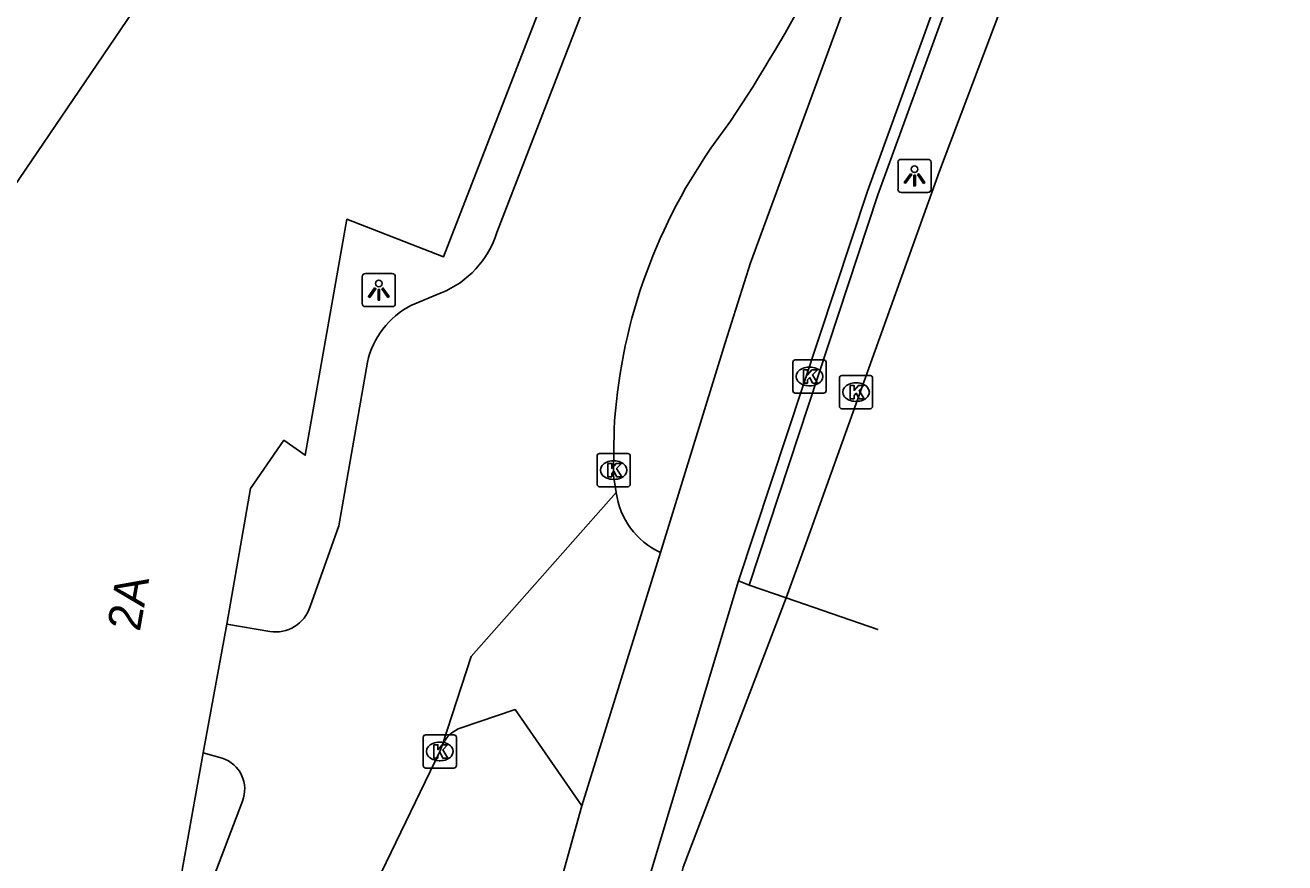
# Model space of a CAD drawing. Extents: x 158132 to 159658, y 385257 to 387209.
# Drawn here: x 159315.62 to 159353.57, y 385360.69 to 385385.92 of the extents above; entities that cross this region are included whole.
import ezdxf

# ---------------------------------------------------------------- set-up
doc = ezdxf.new("R2010")
doc.units = 0
for name, color, linetype in [('IMGEO_Berm_open', 7, 'Continuous'), ('IMGEO_Fietspad_gesloten', 7, 'Continuous'), ('IMGEO_Kolk', 7, 'Continuous'), ('IMGEO_Lichtpunt', 7, 'Continuous'), ('IMGEO_Pand', 7, 'Continuous'), ('IMGEO_Pand_nummerreeks', 7, 'Continuous'), ('IMGEO_Parkeervlak_open', 7, 'Continuous'), ('IMGEO_Rijbaan_lokaal_gesloten', 7, 'Continuous'), ('IMGEO_Rijbaan_lokaal_open', 7, 'Continuous'), ('IMGEO_Voetpad_open', 7, 'Continuous')]:
    doc.layers.add(name, color=color, linetype=linetype)

msp = doc.modelspace()

# ---------------------------------------------------------------- linework, layer by layer
at = {"layer": 'IMGEO_Berm_open'}
msp.add_lwpolyline([(159337.434, 385369.055), (159341.31, 385380.813), (159345.777, 385393.089)], dxfattribs=at)
at = {"layer": 'IMGEO_Fietspad_gesloten'}
for points in [[(159353.565, 385414.672), (159347.632, 385399.1), (159345.432, 385393.179), (159340.99, 385380.922), (159337.107, 385369.181)], [(159334.755, 385370.041), (159336.71, 385376.358), (159337.469, 385378.764), (159341.578, 385389.943)], [(159332.393, 385362.406), (159334.755, 385370.041)], [(159325.605, 385338.172), (159326.704, 385341.948), (159332.393, 385362.406)]]:
    msp.add_lwpolyline(points, dxfattribs=at)
at = {"layer": 'IMGEO_Kolk'}
for p, q in [((159338.745, 385374.916), (159338.745, 385375.768)), ((159338.82, 385375.842), (159339.672, 385375.842)), ((159339.746, 385375.768), (159339.746, 385374.916)), ((159339.233, 385375.622), (159339.258, 385375.622)), ((159340.223, 385375.371), (159341.075, 385375.371)), ((159339.256, 385375.062), (159339.231, 385375.062)), ((159340.148, 385374.445), (159340.148, 385375.297)), ((159340.636, 385375.151), (159340.661, 385375.151)), ((159341.149, 385375.297), (159341.149, 385374.445)), ((159339.672, 385374.842), (159338.82, 385374.842)), ((159340.659, 385374.591), (159340.634, 385374.591)), ((159341.075, 385374.371), (159340.223, 385374.371)), ((159332.846, 385372.095), (159332.846, 385372.947)), ((159332.921, 385373.021), (159333.773, 385373.021)), ((159333.334, 385372.801), (159333.359, 385372.801)), ((159333.847, 385372.947), (159333.847, 385372.095)), ((159333.773, 385372.021), (159332.921, 385372.021)), ((159333.357, 385372.241), (159333.332, 385372.241)), ((159327.609, 385363.62), (159327.609, 385364.472)), ((159327.684, 385364.546), (159328.536, 385364.546)), ((159328.61, 385364.472), (159328.61, 385363.62)), ((159328.097, 385364.326), (159328.122, 385364.326)), ((159328.12, 385363.766), (159328.095, 385363.766)), ((159328.536, 385363.546), (159327.684, 385363.546))]:
    msp.add_line(p, q, dxfattribs=at)
for points in [[(159338.745, 385374.916), (159338.745, 385375.768)], [(159338.82, 385375.842), (159339.672, 385375.842)], [(159339.746, 385375.768), (159339.746, 385374.916)], [(159339.066, 385375.542), (159339.189, 385375.542), (159339.189, 385375.391), (159339.319, 385375.542), (159339.483, 385375.542), (159339.337, 385375.391), (159339.49, 385375.142), (159339.338, 385375.142), (159339.253, 385375.306), (159339.189, 385375.239), (159339.189, 385375.142), (159339.066, 385375.142), (159339.066, 385375.542)], [(159340.223, 385375.371), (159341.075, 385375.371)], [(159340.148, 385374.445), (159340.148, 385375.297)], [(159340.469, 385375.071), (159340.592, 385375.071), (159340.592, 385374.92), (159340.722, 385375.071), (159340.886, 385375.071), (159340.74, 385374.92), (159340.893, 385374.671), (159340.741, 385374.671), (159340.656, 385374.835), (159340.592, 385374.768), (159340.592, 385374.671), (159340.469, 385374.671), (159340.469, 385375.071)], [(159341.149, 385375.297), (159341.149, 385374.445)], [(159339.672, 385374.842), (159338.82, 385374.842)], [(159341.075, 385374.371), (159340.223, 385374.371)], [(159332.846, 385372.095), (159332.846, 385372.947)], [(159332.921, 385373.021), (159333.773, 385373.021)], [(159333.167, 385372.721), (159333.29, 385372.721), (159333.29, 385372.57), (159333.42, 385372.721), (159333.584, 385372.721), (159333.438, 385372.57), (159333.591, 385372.321), (159333.439, 385372.321), (159333.354, 385372.485), (159333.29, 385372.418), (159333.29, 385372.321), (159333.167, 385372.321), (159333.167, 385372.721)], [(159333.847, 385372.947), (159333.847, 385372.095)], [(159333.773, 385372.021), (159332.921, 385372.021)], [(159327.609, 385363.62), (159327.609, 385364.472)], [(159327.684, 385364.546), (159328.536, 385364.546)], [(159328.61, 385364.472), (159328.61, 385363.62)], [(159327.93, 385364.246), (159328.053, 385364.246), (159328.053, 385364.095), (159328.183, 385364.246), (159328.347, 385364.246), (159328.201, 385364.095), (159328.354, 385363.846), (159328.202, 385363.846), (159328.117, 385364.01), (159328.053, 385363.943), (159328.053, 385363.846), (159327.93, 385363.846), (159327.93, 385364.246)], [(159328.536, 385363.546), (159327.684, 385363.546)]]:
    msp.add_lwpolyline(points, dxfattribs=at)
for centre, start, end in [((159338.822, 385375.766), 91.552, 178.448), ((159338.822, 385375.766), 91.552, 178.448), ((159339.67, 385375.766), 1.552, 88.448), ((159339.67, 385375.766), 1.552, 88.448), ((159340.225, 385375.295), 91.552, 178.448), ((159340.225, 385375.295), 91.552, 178.448), ((159341.073, 385375.295), 1.552, 88.448), ((159341.073, 385375.295), 1.552, 88.448), ((159338.822, 385374.918), 181.552, 268.448), ((159338.822, 385374.918), 181.552, 268.448), ((159339.67, 385374.918), 271.552, 358.448), ((159339.67, 385374.918), 271.552, 358.448), ((159340.225, 385374.447), 181.552, 268.448), ((159340.225, 385374.447), 181.552, 268.448), ((159341.073, 385374.447), 271.552, 358.448), ((159341.073, 385374.447), 271.552, 358.448), ((159332.923, 385372.945), 91.552, 178.448), ((159332.923, 385372.945), 91.552, 178.448), ((159333.771, 385372.945), 1.552, 88.448), ((159333.771, 385372.945), 1.552, 88.448), ((159332.923, 385372.097), 181.552, 268.448), ((159332.923, 385372.097), 181.552, 268.448), ((159333.771, 385372.097), 271.552, 358.448), ((159333.771, 385372.097), 271.552, 358.448), ((159327.686, 385364.47), 91.552, 178.448), ((159327.686, 385364.47), 91.552, 178.448), ((159328.534, 385364.47), 1.552, 88.448), ((159328.534, 385364.47), 1.552, 88.448), ((159327.686, 385363.622), 181.552, 268.448), ((159327.686, 385363.622), 181.552, 268.448), ((159328.534, 385363.622), 271.552, 358.448), ((159328.534, 385363.622), 271.552, 358.448)]:
    msp.add_arc(centre, 0.0765, start, end, dxfattribs=at)
for centre, major_axis, ratio, start_param, end_param in [((159339.232, 385375.342), (-0.387, 0.002), 0.722429, 4.712389, 7.853982), ((159339.257, 385375.342), (-0.39, 0.002), 0.717154, 1.570796, 4.712389), ((159340.635, 385374.871), (-0.387, 0.002), 0.722429, 4.712389, 7.853982), ((159340.66, 385374.871), (-0.39, 0.002), 0.717154, 1.570796, 4.712389), ((159333.333, 385372.521), (-0.387, 0.002), 0.722429, 4.712389, 7.853982), ((159333.358, 385372.521), (-0.39, 0.002), 0.717154, 1.570796, 4.712389), ((159328.096, 385364.046), (-0.387, 0.002), 0.722429, 4.712389, 7.853982), ((159328.121, 385364.046), (-0.39, 0.002), 0.717154, 1.570796, 4.712389)]:
    msp.add_ellipse(centre, major_axis=major_axis, ratio=ratio, start_param=start_param, end_param=end_param, dxfattribs=at)
at = {"layer": 'IMGEO_Lichtpunt'}
for p, q in [((159342.815, 385381.882), (159342.007, 385381.882)), ((159342.815, 385381.882), (159342.007, 385381.882)), ((159341.913, 385381.787), (159341.913, 385380.98)), ((159341.913, 385381.787), (159341.913, 385380.98)), ((159342.909, 385380.98), (159342.909, 385381.787)), ((159342.909, 385380.98), (159342.909, 385381.787)), ((159342.007, 385380.886), (159342.815, 385380.886)), ((159342.007, 385380.886), (159342.815, 385380.886)), ((159326.675, 385378.443), (159325.867, 385378.443)), ((159326.675, 385378.443), (159325.867, 385378.443)), ((159325.773, 385378.348), (159325.773, 385377.541)), ((159325.773, 385378.348), (159325.773, 385377.541)), ((159326.769, 385377.541), (159326.769, 385378.348)), ((159326.769, 385377.541), (159326.769, 385378.348)), ((159325.867, 385377.447), (159326.675, 385377.447)), ((159325.867, 385377.447), (159326.675, 385377.447))]:
    msp.add_line(p, q, dxfattribs=at)
for points in [[(159342.287, 385381.451), (159342.326, 385381.423), (159342.138, 385381.161), (159342.1, 385381.188), (159342.287, 385381.451)], [(159342.499, 385381.423), (159342.537, 385381.45), (159342.724, 385381.188), (159342.685, 385381.16), (159342.499, 385381.423)], [(159342.389, 385381.403), (159342.436, 385381.403), (159342.436, 385381.081), (159342.389, 385381.081), (159342.389, 385381.403)], [(159326.147, 385378.012), (159326.186, 385377.984), (159325.998, 385377.722), (159325.96, 385377.749), (159326.147, 385378.012)], [(159326.359, 385377.984), (159326.397, 385378.011), (159326.584, 385377.749), (159326.545, 385377.721), (159326.359, 385377.984)], [(159326.249, 385377.964), (159326.296, 385377.964), (159326.296, 385377.642), (159326.249, 385377.642), (159326.249, 385377.964)]]:
    msp.add_lwpolyline(points, dxfattribs=at)
for centre in [(159342.412, 385381.585), (159326.272, 385378.146)]:
    msp.add_circle(centre, 0.0994, dxfattribs=at)
for centre, start, end in [((159342.007, 385381.787), 90, 180), ((159342.007, 385381.787), 90, 180), ((159342.815, 385381.787), 0, 90), ((159342.815, 385381.787), 0, 90), ((159342.007, 385380.98), 180, 270), ((159342.007, 385380.98), 180, 270), ((159342.815, 385380.98), 270, 0), ((159342.815, 385380.98), 270, 360), ((159325.867, 385378.348), 90, 180), ((159325.867, 385378.348), 90, 180), ((159326.675, 385378.348), 0, 90), ((159326.675, 385378.348), 0, 90), ((159325.867, 385377.541), 180, 270), ((159325.867, 385377.541), 180, 270), ((159326.675, 385377.541), 270, 0), ((159326.675, 385377.541), 270, 360)]:
    msp.add_arc(centre, 0.0946, start, end, dxfattribs=at)
at = {"layer": 'IMGEO_Pand'}
for points in [[(159316.979, 385343.527), (159311.61, 385347.185), (159312.454, 385348.445), (159314.231, 385348.803), (159318.908, 385355.721), (159308.981, 385362.497), (159311.29, 385375.202), (159321.933, 385390.864)], [(159331.236, 385386.718), (159328.225, 385378.947), (159325.306, 385380.08), (159324.057, 385372.971), (159323.416, 385373.419), (159322.404, 385371.963), (159321.69, 385367.879)], [(159321.69, 385367.879), (159320.981, 385364.001)], [(159320.981, 385364.001), (159319.436, 385355.372)]]:
    msp.add_lwpolyline(points, dxfattribs=at)
at = {"layer": 'IMGEO_Parkeervlak_open'}
for points in [[(159336.869, 385383.033), (159336.278, 385382.216)], [(159333.359, 385373.735), (159333.346, 385372.521), (159333.341, 385372.36), (159333.426, 385371.844)], [(159328.193, 385364.252), (159329.057, 385366.903), (159333.426, 385371.844)], [(159332.393, 385362.406), (159330.382, 385365.305), (159328.758, 385364.759)], [(159328.193, 385364.252), (159328.108, 385364.046), (159322.815, 385353.097)]]:
    msp.add_lwpolyline(points, dxfattribs=at)
for centre, radius, start, end in [((159296.758, 385409.689), 48.16, 326.3941, 332.3287), ((159349.802, 385372.818), 16.469, 145.2057, 176.8093), ((159335.731, 385372.151), 2.325, 187.598, 245.1902), ((159329.067, 385363.846), 0.964, 108.7187, 155.0875)]:
    msp.add_arc(centre, radius, start, end, dxfattribs=at)
at = {"layer": 'IMGEO_Rijbaan_lokaal_gesloten'}
for points in [[(159347.31, 385392.51), (159343.163, 385381.525), (159339.1, 385370.193), (159338.547, 385368.674)], [(159338.547, 385368.674), (159335.444, 385360.564), (159335.053, 385358.921)], [(159338.547, 385368.674), (159341.306, 385367.718), (159341.306, 385367.718)]]:
    msp.add_lwpolyline(points, dxfattribs=at)
at = {"layer": 'IMGEO_Rijbaan_lokaal_open'}
for points in [[(159337.107, 385369.181), (159334.093, 385359.173)], [(159337.107, 385369.181), (159337.434, 385369.055)], [(159338.547, 385368.674), (159337.434, 385369.055)]]:
    msp.add_lwpolyline(points, dxfattribs=at)
at = {"layer": 'IMGEO_Voetpad_open'}
for points in [[(159332.654, 385386.979), (159329.826, 385379.678)], [(159328.155, 385377.86), (159327.237, 385377.483)], [(159325.93, 385375.772), (159325.066, 385370.846), (159324.203, 385368.408)], [(159322.988, 385367.659), (159321.69, 385367.879)], [(159320.981, 385364.001), (159321.558, 385363.84)], [(159322.165, 385362.553), (159319.436, 385355.372)]]:
    msp.add_lwpolyline(points, dxfattribs=at)
for centre, radius, start, end in [((159327.073, 385380.532), 2.883, 292.0527, 342.7725), ((159328.433, 385375.215), 2.564, 117.8029, 167.4461), ((159323.163, 385368.735), 1.09, 260.7668, 342.5376), ((159321.26, 385362.913), 0.974, 338.3143, 72.1865)]:
    msp.add_arc(centre, radius, start, end, dxfattribs=at)

# ---------------------------------------------------------------- texts
at = {"layer": 'IMGEO_Pand_nummerreeks'}
msp.add_text('2A', height=1, rotation=79.8646, dxfattribs=at).set_placement((159319.071, 385367.633))

doc.saveas('drawing.dxf')
